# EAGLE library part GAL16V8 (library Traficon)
High Performance E2CMOS PLD Generic Array Logic?
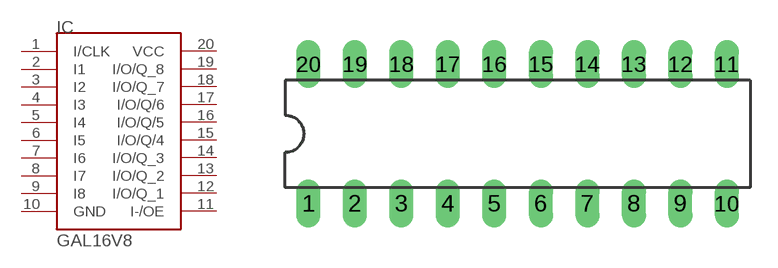
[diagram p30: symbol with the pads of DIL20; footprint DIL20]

Designator prefix IC

## GAL16V8  [DIL20]
1  I/CLK
2  I1
3  I2
4  I3
5  I4
6  I5
7  I6
8  I7
9  I8
10  GND  pas
11  I-/OE
12  I/O/Q_1
13  I/O/Q_2
14  I/O/Q_3
15  I/O/Q/4
16  I/O/Q/5
17  I/O/Q/6
18  I/O/Q_7
19  I/O/Q_8
20  VCC  pas

## Footprint DIL20 (pad centres in mm)
Dual In Line Package
drill 0.813 long: 1 -11.43,-3.81; 2 -8.89,-3.81; 3 -6.35,-3.81; 4 -3.81,-3.81; 5 -1.27,-3.81; 6 1.27,-3.81; 7 3.81,-3.81; 8 6.35,-3.81; 9 8.89,-3.81; 10 11.43,-3.81; 11 11.43,3.81; 12 8.89,3.81; 13 6.35,3.81; 14 3.81,3.81; 15 1.27,3.81; 16 -1.27,3.81; 17 -3.81,3.81; 18 -6.35,3.81; 19 -8.89,3.81; 20 -11.43,3.81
